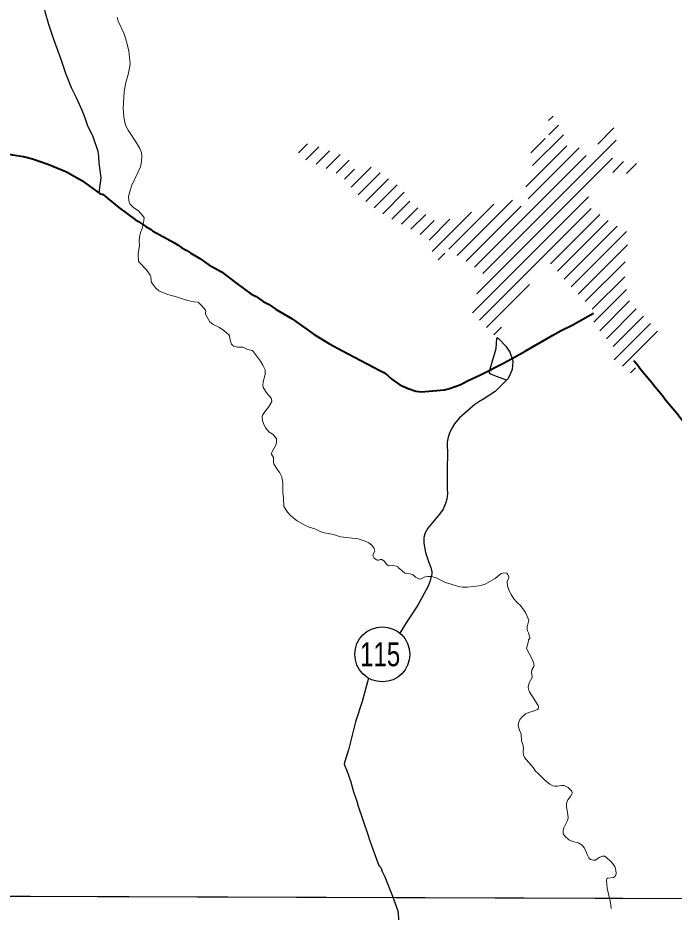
# Model space of a CAD drawing. Extents: x -1643653 to 4543381, y 1624270 to 13878484.
# Drawn here: x 614173 to 616089, y 8909821 to 8912433 of the extents above; entities that cross this region are included whole.
import ezdxf
from ezdxf.enums import TextEntityAlignment as Align

# ---------------------------------------------------------------- set-up
doc = ezdxf.new("R2010")
doc.units = 0
doc.header["$LTSCALE"] = 200
doc.layers.add('1', color=7, linetype='Continuous', lineweight=13)
doc.layers.add('6', color=7, linetype='Continuous', lineweight=13)

msp = doc.modelspace()

# ---------------------------------------------------------------- linework, layer by layer
at = {"layer": '1', "lineweight": 25}
msp.add_spline([(814781, 9009175.5), (814787.2, 9009173.4), (814796.9, 9009173.4), (814799.4, 9009172.4), (814805.1, 9009174.5), (814805.6, 9009176.5), (814811.7, 9009179.5), (814811.7, 9009179.5), (814801.5, 9009181), (814790.7, 9009181.5), (814784.1, 9009183.1), (814777.4, 9009185.1), (814778.4, 9009175.5)], degree=3, dxfattribs=at)
at = {"layer": '6'}
for p, q in [((615722.8, 8912133.8), (615735.8, 8912146.7)), ((615723.1, 8912091.6), (615751.6, 8912120.1)), ((615866.2, 8912064.9), (615913.5, 8912112.3)), ((615530.8, 8911687.2), (615920.2, 8912076.6)), ((615670.7, 8912039.2), (615712.3, 8912080.8)), ((615675.8, 8912001.9), (615765.9, 8912092)), ((614991.9, 8912039.2), (615018.6, 8912065.9)), ((615014.2, 8912019), (615051.5, 8912056.4)), ((615043.8, 8912006.3), (615082.5, 8912044.9)), ((615656.6, 8911940.3), (615776.4, 8912060.1)), ((615663.6, 8911904.8), (615812.3, 8912053.5)), ((615073.5, 8911993.6), (615114.1, 8912034.1)), ((615102.3, 8911979.9), (615140.1, 8912017.8)), ((615506.2, 8911705), (615832.4, 8912031.2)), ((615513.3, 8911627.3), (615909.8, 8912023.7)), ((615145.9, 8911938.7), (615204.6, 8911997.4)), ((615910.3, 8911981.8), (615942, 8912013.5)), ((615950.2, 8911979.3), (615979.5, 8912008.6)), ((615127, 8911962.2), (615156.3, 8911991.4)), ((615166.7, 8911917), (615230.7, 8911981)), ((615189.2, 8911897.1), (615255.5, 8911963.4)), ((615213, 8911878.5), (615280.3, 8911945.8)), ((615238.2, 8911861.3), (615301.4, 8911924.5)), ((615265.1, 8911845.7), (615317.8, 8911898.4)), ((615431.6, 8911757.6), (615562.9, 8911888.9)), ((615456.2, 8911739.8), (615617.5, 8911901.2)), ((615500.3, 8911571.8), (615839.7, 8911911.2)), ((615292.7, 8911830.9), (615340.7, 8911878.9)), ((615382.8, 8911751.2), (615497.4, 8911865.9)), ((615481.7, 8911722.9), (615642.7, 8911883.9)), ((615521.1, 8911550.2), (615847.5, 8911876.6)), ((615320.2, 8911816), (615363.8, 8911859.6)), ((615347.4, 8911800.8), (615388.4, 8911841.7)), ((615373.7, 8911784.6), (615434.8, 8911845.7)), ((615728.4, 8911715.1), (615872.1, 8911858.8)), ((615748.9, 8911693.2), (615897, 8911841.2)), ((615768.1, 8911669.9), (615923.5, 8911825.3)), ((615788.8, 8911648.1), (615950.1, 8911809.5)), ((615809.4, 8911626.3), (615953.2, 8911770.2)), ((615400.2, 8911726.3), (615420.1, 8911746.2)), ((615830, 8911604.6), (615946.5, 8911721.1)), ((615541.9, 8911528.6), (615667.5, 8911654.2)), ((615850.5, 8911582.5), (615945.5, 8911677.5)), ((615854.5, 8911544.2), (615950.1, 8911639.7)), ((615872.1, 8911519.3), (615959.2, 8911606.5)), ((615891.5, 8911496.3), (615978.4, 8911583.2)), ((615911.6, 8911474), (616000, 8911562.4)), ((615562.9, 8911507.2), (615585.5, 8911529.7)), ((615914.5, 8911434.4), (616020.8, 8911540.8)), ((615938.9, 8911416.4), (616040.5, 8911518)), ((615961.7, 8911396.8), (615976.5, 8911411.6)), ((574653.9, 8910009.3), (626625.7, 8909822.1))]:
    msp.add_line(p, q, dxfattribs=at)
at = {"layer": '6', "lineweight": 25}
msp.add_line((615138.8, 8910295.4), (615126.6, 8910258.3), dxfattribs=at)
for points in [[(614245.5, 8912486.2), (614248.5, 8912465.4), (614251.4, 8912452.5), (614261.7, 8912415.4), (614276.3, 8912371.6), (614298, 8912313.3), (614311.5, 8912271.9), (614311.5, 8912271.9), (614328.6, 8912229.8), (614343.1, 8912200.7), (614360.8, 8912161.7), (614367, 8912144.3)], [(614367, 8912144.3), (614375.3, 8912120.7), (614391.5, 8912087.1), (614405.8, 8912044.1), (614407.9, 8912028.6), (614409.2, 8912009.7), (614415.2, 8911965.8), (614409.2, 8911922.5)], [(615599.9, 8911375), (615570.6, 8911385.8), (615552.6, 8911394.1), (615550.1, 8911396.3), (615552, 8911408.1), (615569.5, 8911467.6), (615571.8, 8911497.7), (615572.6, 8911500), (615576.1, 8911497.3), (615598, 8911474.4), (615609.3, 8911456.9), (615617.4, 8911434.8), (615618, 8911429.4), (615616.8, 8911406.4), (615607.9, 8911385.5), (615603.3, 8911379.1), (615567.2, 8911342.2), (615530.8, 8911318.5), (615518.9, 8911311.9), (615507.1, 8911303.9), (615461.7, 8911264.1), (615448.1, 8911247.4), (615440.7, 8911235.9), (615434.2, 8911222.9), (615429.1, 8911208.4), (615426.1, 8911193.8), (615427.6, 8911155.1), (615426.4, 8911122.4), (615426.8, 8911058.8), (615427.6, 8911043.4), (615425.9, 8911028), (615422.1, 8911015), (615414.6, 8910998.4), (615403.9, 8910983.4), (615369.6, 8910943.1), (615362.5, 8910929), (615358.7, 8910915.2), (615358.7, 8910898.9), (615363.5, 8910871.4), (615371.8, 8910845.5), (615378.5, 8910828.5), (615382, 8910815.5), (615381.8, 8910809.8), (615377.1, 8910788.9), (615371.3, 8910773.5), (615341.2, 8910717.8), (615307.1, 8910666.5), (615288.4, 8910636.1)], [(615196.8, 8910504.9), (615177.9, 8910436.4), (615158.9, 8910377.1), (615138.8, 8910295.4)], [(615126.6, 8910258.3), (615125.9, 8910253.6), (615134.7, 8910231.8), (615144, 8910204.7), (615152.8, 8910172.4), (615162.3, 8910145.7), (615166.8, 8910130.4), (615195.1, 8910047.8), (615199.5, 8910032.8), (615209.6, 8910005.2)], [(615209.6, 8910005.2), (615227, 8909957.6), (615232.7, 8909951.5), (615237, 8909940.3), (615244.4, 8909924.9), (615267.1, 8909868.1), (615282, 8909824.9)], [(615282, 8909824.9), (615292.5, 8909716.1), (615320.5, 8909565.2), (615327.5, 8909531.6), (615344.7, 8909497.9), (615365.9, 8909445.9), (615390.2, 8909408.2), (615414.6, 8909376.6), (615454.1, 8909327.6), (615483.5, 8909293.9), (615556.6, 8909207.2), (615624.7, 8909143.6), (615643.3, 8909127.9), (615658.6, 8909118.9)]]:
    msp.add_lwpolyline(points, dxfattribs=at)
at = {"layer": '6'}
for points in [[(614462.6, 8912435.7), (614465.5, 8912423.8), (614481.8, 8912388.7), (614488.3, 8912371.2), (614496.7, 8912337), (614500.2, 8912308.2), (614500.5, 8912297.9), (614495.6, 8912271.6), (614487.7, 8912244.4), (614483.1, 8912218.1), (614480.7, 8912168.7), (614482.5, 8912145.7), (614484.5, 8912132.9)], [(614462.6, 8912435.7), (614465.5, 8912423.8), (614481.8, 8912388.7), (614488.3, 8912371.2), (614496.7, 8912337), (614500.2, 8912308.2), (614500.5, 8912297.9), (614495.6, 8912271.6), (614487.7, 8912244.4), (614483.1, 8912218.1), (614480.7, 8912168.7), (614482.5, 8912145.7), (614484.5, 8912132.9)], [(614484.5, 8912132.9), (614488.5, 8912118.5), (614494.8, 8912105.6), (614519, 8912068.7), (614528.5, 8912052.3), (614533.6, 8912040.3), (614535.2, 8912029.2), (614534.1, 8912013.9), (614530.5, 8911998.8), (614524.3, 8911983.7), (614505.6, 8911945.2), (614498.3, 8911923.7), (614495.8, 8911911), (614498.1, 8911894.5), (614499.6, 8911890.4), (614505.2, 8911884.2), (614511.7, 8911878.7), (614525.4, 8911869.5), (614537.6, 8911855.5), (614541.2, 8911849.9), (614540.9, 8911842.1), (614539, 8911829.5), (614535.8, 8911818.4), (614530.9, 8911806.4), (614528.1, 8911793), (614527.1, 8911782.7), (614527.6, 8911768.3), (614524, 8911744.5), (614525, 8911723.2), (614527.2, 8911719.7), (614548.6, 8911697.1), (614559.2, 8911682.3), (614561, 8911678.1), (614562.1, 8911665.3), (614563.3, 8911660.1), (614575.8, 8911644.3), (614584.1, 8911636.2)], [(614484.5, 8912132.9), (614488.5, 8912118.5), (614494.8, 8912105.6), (614519, 8912068.7), (614528.5, 8912052.3), (614533.6, 8912040.3), (614535.2, 8912029.2), (614534.1, 8912013.9), (614530.5, 8911998.8), (614524.3, 8911983.7), (614505.6, 8911945.2), (614498.3, 8911923.7), (614495.8, 8911911), (614498.1, 8911894.5), (614499.6, 8911890.4), (614505.2, 8911884.2), (614511.7, 8911878.7), (614525.4, 8911869.5), (614537.6, 8911855.5), (614541.2, 8911849.9), (614540.9, 8911842.1), (614539, 8911829.5), (614535.8, 8911818.4), (614530.9, 8911806.4), (614528.1, 8911793), (614527.1, 8911782.7), (614527.6, 8911768.3), (614524, 8911744.5), (614525, 8911723.2), (614527.2, 8911719.7), (614548.6, 8911697.1), (614559.2, 8911682.3), (614561, 8911678.1), (614562.1, 8911665.3), (614563.3, 8911660.1), (614575.8, 8911644.3), (614584.1, 8911636.2)], [(614584.1, 8911636.2), (614584.1, 8911636.2), (614608.1, 8911626), (614620.1, 8911622.5), (614632.8, 8911620.1), (614646.4, 8911614.5), (614669.5, 8911607.6), (614686.7, 8911603.6), (614699.1, 8911603.5)], [(614584.1, 8911636.2), (614584.1, 8911636.2), (614608.1, 8911626), (614620.1, 8911622.5), (614632.8, 8911620.1), (614646.4, 8911614.5), (614669.5, 8911607.6), (614686.7, 8911603.6), (614699.1, 8911603.5)], [(614699.1, 8911603.5), (614709.6, 8911592.7), (614721, 8911579.5), (614721.7, 8911577.4), (614720.5, 8911571.3), (614720.9, 8911568.5), (614725.2, 8911559.5), (614733.7, 8911545.2), (614743, 8911537.5), (614761.4, 8911528.7), (614774.6, 8911520.4), (614789, 8911508.1), (614790.7, 8911504.8), (614791.9, 8911496.1), (614796.7, 8911480.4), (614798.5, 8911478), (614803.8, 8911474.7), (614814.1, 8911471.6), (614829.7, 8911471.7), (614843.8, 8911465.2), (614857.7, 8911461.5)], [(614699.1, 8911603.5), (614709.6, 8911592.7), (614721, 8911579.5), (614721.7, 8911577.4), (614720.5, 8911571.3), (614720.9, 8911568.5), (614725.2, 8911559.5), (614733.7, 8911545.2), (614743, 8911537.5), (614761.4, 8911528.7), (614774.6, 8911520.4), (614789, 8911508.1), (614790.7, 8911504.8), (614791.9, 8911496.1), (614796.7, 8911480.4), (614798.5, 8911478), (614803.8, 8911474.7), (614814.1, 8911471.6), (614829.7, 8911471.7), (614843.8, 8911465.2), (614857.7, 8911461.5)], [(614857.7, 8911461.5), (614881.8, 8911430.8), (614888.6, 8911419.2), (614894.8, 8911405.2)], [(614857.7, 8911461.5), (614881.8, 8911430.8), (614888.6, 8911419.2), (614894.8, 8911405.2)], [(614894.8, 8911405.2), (614895.4, 8911391.4), (614888.9, 8911370.2), (614888.4, 8911360.8), (614889.1, 8911353.8), (614899.5, 8911337.6), (614912.4, 8911323), (614913.7, 8911319.3), (614914.2, 8911313.3), (614904.9, 8911296.6), (614891.1, 8911278.7), (614887.5, 8911272.7), (614886.7, 8911268.4), (614887.5, 8911257.1), (614891.3, 8911245.4), (614896.7, 8911234.7), (614905.3, 8911224.8), (614918.6, 8911216.5), (614926.2, 8911207.2), (614927.8, 8911204), (614928.2, 8911197.9), (614926.8, 8911187.5), (614914.6, 8911165.4), (614913.8, 8911159.4), (614919.2, 8911149.3), (614919.5, 8911135.1), (614920.4, 8911130.5), (614928.7, 8911116), (614938, 8911104.3), (614943.4, 8911093.3), (614946.1, 8911074.3), (614946.5, 8911046), (614948.7, 8911031.5), (614949.6, 8911006.3), (614960.5, 8910989.7), (614969.6, 8910979.2), (614979.4, 8910970.7), (614988.7, 8910963.9), (615010.6, 8910951.4), (615020.6, 8910946.9), (615040, 8910940.5), (615058, 8910932.4), (615068.1, 8910929.7), (615094.7, 8910924.8), (615114.8, 8910917.8), (615166.8, 8910911.8), (615187.2, 8910905), (615197.9, 8910900.2), (615206.5, 8910893.3), (615213.6, 8910883.4), (615215, 8910876), (615209.8, 8910865.4), (615209.1, 8910862.7), (615213.4, 8910855.6), (615220.2, 8910850.1), (615223.2, 8910849.3), (615226.8, 8910849.7), (615230.9, 8910851.5), (615235.7, 8910851.1), (615242.4, 8910846.7), (615250.7, 8910837.1), (615255.1, 8910833.3), (615267.9, 8910833.6), (615278.9, 8910832), (615282.1, 8910830.2)], [(614894.8, 8911405.2), (614895.4, 8911391.4), (614888.9, 8911370.2), (614888.4, 8911360.8), (614889.1, 8911353.8), (614899.5, 8911337.6), (614912.4, 8911323), (614913.7, 8911319.3), (614914.2, 8911313.3), (614904.9, 8911296.6), (614891.1, 8911278.7), (614887.5, 8911272.7), (614886.7, 8911268.4), (614887.5, 8911257.1), (614891.3, 8911245.4), (614896.7, 8911234.7), (614905.3, 8911224.8), (614918.6, 8911216.5), (614926.2, 8911207.2), (614927.8, 8911204), (614928.2, 8911197.9), (614926.8, 8911187.5), (614914.6, 8911165.4), (614913.8, 8911159.4), (614919.2, 8911149.3), (614919.5, 8911135.1), (614920.4, 8911130.5), (614928.7, 8911116), (614938, 8911104.3), (614943.4, 8911093.3), (614946.1, 8911074.3), (614946.5, 8911046), (614948.7, 8911031.5), (614949.6, 8911006.3), (614960.5, 8910989.7), (614969.6, 8910979.2), (614979.4, 8910970.7), (614988.7, 8910963.9), (615010.6, 8910951.4), (615020.6, 8910946.9), (615040, 8910940.5), (615058, 8910932.4), (615068.1, 8910929.7), (615094.7, 8910924.8), (615114.8, 8910917.8), (615166.8, 8910911.8), (615187.2, 8910905), (615197.9, 8910900.2), (615206.5, 8910893.3), (615213.6, 8910883.4), (615215, 8910876), (615209.8, 8910865.4), (615209.1, 8910862.7), (615213.4, 8910855.6), (615220.2, 8910850.1), (615223.2, 8910849.3), (615226.8, 8910849.7), (615230.9, 8910851.5), (615235.7, 8910851.1), (615242.4, 8910846.7), (615250.7, 8910837.1), (615255.1, 8910833.3), (615267.9, 8910833.6), (615278.9, 8910832), (615282.1, 8910830.2)], [(615282.1, 8910830.2), (615283.3, 8910828.4), (615301.8, 8910812), (615305.6, 8910810.9), (615317.4, 8910809.9), (615327, 8910806.2), (615334.1, 8910800.2), (615345.7, 8910794.2), (615350.8, 8910794.5), (615359.4, 8910799.7), (615362.8, 8910800.9), (615370.9, 8910802.2), (615381.1, 8910801.7), (615392.8, 8910798.4), (615422.1, 8910783.9), (615463.6, 8910771.7), (615471.6, 8910770.6), (615485.6, 8910770.5), (615518.7, 8910774.5), (615528.2, 8910776.4), (615537.8, 8910779.3), (615566.4, 8910796.3), (615584.6, 8910810.5), (615590.8, 8910812.2), (615600.7, 8910811.2), (615603.2, 8910808.9), (615606.8, 8910802), (615606.7, 8910796.5), (615602.9, 8910789.8), (615602.2, 8910786.7), (615603.2, 8910774.1), (615607.3, 8910759.9), (615613.3, 8910748.7), (615621.7, 8910736.7), (615632.2, 8910724.8), (615640.6, 8910717.5), (615655, 8910696.9)], [(615282.1, 8910830.2), (615283.3, 8910828.4), (615301.8, 8910812), (615305.6, 8910810.9), (615317.4, 8910809.9), (615327, 8910806.2), (615334.1, 8910800.2), (615345.7, 8910794.2), (615350.8, 8910794.5), (615359.4, 8910799.7), (615362.8, 8910800.9), (615370.9, 8910802.2), (615381.1, 8910801.7), (615392.8, 8910798.4), (615422.1, 8910783.9), (615463.6, 8910771.7), (615471.6, 8910770.6), (615485.6, 8910770.5), (615518.7, 8910774.5), (615528.2, 8910776.4), (615537.8, 8910779.3), (615566.4, 8910796.3), (615584.6, 8910810.5), (615590.8, 8910812.2), (615600.7, 8910811.2), (615603.2, 8910808.9), (615606.8, 8910802), (615606.7, 8910796.5), (615602.9, 8910789.8), (615602.2, 8910786.7), (615603.2, 8910774.1), (615607.3, 8910759.9), (615613.3, 8910748.7), (615621.7, 8910736.7), (615632.2, 8910724.8), (615640.6, 8910717.5), (615655, 8910696.9)], [(615655, 8910696.9), (615656, 8910695), (615665, 8910674.5), (615660.6, 8910655.1), (615659.8, 8910646.5), (615660.9, 8910642.9), (615664.4, 8910636.8), (615668, 8910623.7), (615667.6, 8910622), (615664, 8910616.7), (615663.2, 8910608.5), (615658, 8910591.3), (615674.8, 8910560.7), (615678.6, 8910550.5), (615680.5, 8910541.2), (615679.6, 8910538.6), (615673.4, 8910528.9), (615673.3, 8910520.8), (615674.8, 8910510.7), (615674.5, 8910507.1), (615665.9, 8910491.1), (615662.8, 8910478.6), (615664, 8910473.1), (615667.5, 8910464.5), (615692.6, 8910424.9), (615693.7, 8910422.2), (615692.8, 8910415.3), (615690.4, 8910413.3), (615677.6, 8910408), (615667.7, 8910405.9), (615654.9, 8910400.8), (615643.2, 8910389.5), (615638, 8910382.3), (615634.6, 8910373.3), (615634, 8910366.5), (615637.8, 8910353.2), (615642.9, 8910341.4), (615643.7, 8910321.8), (615647.4, 8910310.9), (615649.7, 8910301.3), (615648.6, 8910289.1), (615649.3, 8910280.6), (615652.9, 8910273.4), (615657.9, 8910266.5), (615678, 8910244), (615684.8, 8910233.2), (615691.8, 8910227.6), (615712.5, 8910205.7), (615726.4, 8910195.1), (615735.1, 8910190.5), (615740.5, 8910189), (615748.6, 8910189.6), (615760.2, 8910191.7), (615768.2, 8910191.4), (615779.6, 8910185.2), (615787.6, 8910178.1), (615790.3, 8910174.6), (615791.2, 8910169.9), (615790.2, 8910166.1), (615787, 8910159.5), (615778.9, 8910148.9), (615775.1, 8910139), (615775.4, 8910128.9), (615779, 8910106.3), (615779.6, 8910095.5)], [(615655, 8910696.9), (615656, 8910695), (615665, 8910674.5), (615660.6, 8910655.1), (615659.8, 8910646.5), (615660.9, 8910642.9), (615664.4, 8910636.8), (615668, 8910623.7), (615667.6, 8910622), (615664, 8910616.7), (615663.2, 8910608.5), (615658, 8910591.3), (615674.8, 8910560.7), (615678.6, 8910550.5), (615680.5, 8910541.2), (615679.6, 8910538.6), (615673.4, 8910528.9), (615673.3, 8910520.8), (615674.8, 8910510.7), (615674.5, 8910507.1), (615665.9, 8910491.1), (615662.8, 8910478.6), (615664, 8910473.1), (615667.5, 8910464.5), (615692.6, 8910424.9), (615693.7, 8910422.2), (615692.8, 8910415.3), (615690.4, 8910413.3), (615677.6, 8910408), (615667.7, 8910405.9), (615654.9, 8910400.8), (615643.2, 8910389.5), (615638, 8910382.3), (615634.6, 8910373.3), (615634, 8910366.5), (615637.8, 8910353.2), (615642.9, 8910341.4), (615643.7, 8910321.8), (615647.4, 8910310.9), (615649.7, 8910301.3), (615648.6, 8910289.1), (615649.3, 8910280.6), (615652.9, 8910273.4), (615657.9, 8910266.5), (615678, 8910244), (615684.8, 8910233.2), (615691.8, 8910227.6), (615712.5, 8910205.7), (615726.4, 8910195.1), (615735.1, 8910190.5), (615740.5, 8910189), (615748.6, 8910189.6), (615760.2, 8910191.7), (615768.2, 8910191.4), (615779.6, 8910185.2), (615787.6, 8910178.1), (615790.3, 8910174.6), (615791.2, 8910169.9), (615790.2, 8910166.1), (615787, 8910159.5), (615778.9, 8910148.9), (615775.1, 8910139), (615775.4, 8910128.9), (615779, 8910106.3), (615779.6, 8910095.5)], [(615779.6, 8910095.5), (615777.8, 8910089), (615767.1, 8910068), (615765.5, 8910058.6), (615765.6, 8910051.5), (615766.8, 8910047.7), (615773.9, 8910038.9), (615776.6, 8910037.6), (615782, 8910032.8), (615792.4, 8910027.4), (615808.9, 8910024.1), (615821.1, 8910017.4), (615827.3, 8910008), (615836, 8909987.3), (615840.8, 8909979.7), (615845.5, 8909975.1), (615853.4, 8909973.2), (615858.7, 8909973.1)], [(615779.6, 8910095.5), (615777.8, 8910089), (615767.1, 8910068), (615765.5, 8910058.6), (615765.6, 8910051.5), (615766.8, 8910047.7), (615773.9, 8910038.9), (615776.6, 8910037.6), (615782, 8910032.8), (615792.4, 8910027.4), (615808.9, 8910024.1), (615821.1, 8910017.4), (615827.3, 8910008), (615836, 8909987.3), (615840.8, 8909979.7), (615845.5, 8909975.1), (615853.4, 8909973.2), (615858.7, 8909973.1)], [(615858.7, 8909973.1), (615872.3, 8909982.2), (615872.3, 8909982.2), (615880.5, 8909984.9), (615885.6, 8909985), (615890.5, 8909981.6), (615906.4, 8909966.9), (615915.9, 8909954.7), (615919.4, 8909943.5), (615920.1, 8909933.2), (615918.5, 8909928), (615915.6, 8909924.2), (615912.6, 8909922.4), (615895.5, 8909920.7), (615893.3, 8909918.3), (615891.8, 8909914.3), (615893.8, 8909891.8), (615903, 8909853.2), (615904.8, 8909843), (615905.3, 8909832)], [(615858.7, 8909973.1), (615872.3, 8909982.2), (615872.3, 8909982.2), (615880.5, 8909984.9), (615885.6, 8909985), (615890.5, 8909981.6), (615906.4, 8909966.9), (615915.9, 8909954.7), (615919.4, 8909943.5), (615920.1, 8909933.2), (615918.5, 8909928), (615915.6, 8909924.2), (615912.6, 8909922.4), (615895.5, 8909920.7), (615893.3, 8909918.3), (615891.8, 8909914.3), (615893.8, 8909891.8), (615903, 8909853.2), (615904.8, 8909843), (615905.3, 8909832)]]:
    msp.add_lwpolyline(points, dxfattribs=at)
at = {"layer": '6', "lineweight": 40}
for points in [[(614095.5, 8912045.1), (614137.1, 8912037.7), (614156.6, 8912033.3), (614189.2, 8912028.5), (614215.5, 8912021.7), (614263.5, 8912005.4), (614314.9, 8911983.3), (614359.3, 8911958.1), (614413.5, 8911919.6), (614418.7, 8911918.6), (614421.7, 8911917.2), (614435.2, 8911906.1)], [(614435.2, 8911906.1), (614467.8, 8911879.5), (614516.5, 8911843.4), (614525, 8911838.5), (614546.8, 8911823.9), (614561.7, 8911815.5), (614566.3, 8911811.2), (614628, 8911777.5), (614641.1, 8911769.4), (614651.5, 8911761.7), (614666.3, 8911753.9), (614677.9, 8911746.1), (614704.5, 8911730.6), (614730.4, 8911712.3), (614767.2, 8911691.7), (614812.1, 8911658)], [(614812.1, 8911658), (614834.3, 8911641.2), (614853.5, 8911627.7), (614868.4, 8911619.3), (614889.4, 8911605.2), (614904.7, 8911597), (614927.5, 8911582), (614973.7, 8911554), (615037.8, 8911508.7), (615082.7, 8911481.4), (615119.3, 8911462), (615230, 8911403.5)], [(615622.9, 8911442.5), (615654.7, 8911459.9), (615735.5, 8911507.1), (615759.3, 8911519.9), (615791.8, 8911536), (615853.7, 8911570.5)], [(615230, 8911403.5), (615241.5, 8911397.4), (615253.3, 8911388.6), (615265.3, 8911377.7), (615288.5, 8911361.6), (615312.4, 8911350.8), (615334.8, 8911342.9), (615350.2, 8911341), (615419.2, 8911347.2), (615433.5, 8911350.8), (615466.3, 8911362.9), (615486, 8911373.3), (615523.5, 8911390.4), (615590.8, 8911424.9), (615622.9, 8911442.5)]]:
    msp.add_lwpolyline(points, dxfattribs=at)
at = {"layer": '6'}
msp.add_lwpolyline([(618535.2, 8909853.3), (607574.3, 8909890.7), (607543.3, 8898835.3), (618504.2, 8898795.8)], close=True, dxfattribs=at)
at = {"layer": '6', "lineweight": 25}
msp.add_circle((615237.1, 8910574.3), 80.3, dxfattribs=at)
at = {"layer": '6', "lineweight": 40}
msp.add_spline([(615971.7, 8911432.5), (616138.5, 8911227.2), (616313.3, 8911009), (616504.8, 8910771.9), (616895.5, 8910293.3), (617079.2, 8910062.8), (617725.5, 8909265.3), (618056.1, 8908857.7), (618263.2, 8908603.7), (618306.6, 8908556.9), (618336.6, 8908483.4), (618463.5, 8908212.8), (618533.7, 8908055.7), (618557.1, 8908012.3), (618590.5, 8907985.6), (618640.6, 8907962.2), (618764.1, 8907925.4), (618847.6, 8907882), (618877.7, 8907865.3), (618937.8, 8907811.8), (618997.9, 8907778.4), (619028, 8907745), (619141.5, 8907698.2), (619241.7, 8907674.8), (619372, 8907724.9), (619488.8, 8907801.8), (619552.3, 8907878.6), (619575.7, 8907905.4), (619599.1, 8907898.7), (619632.5, 8907871.9), (619679.2, 8907871.9), (619782.8, 8907918.7), (619872.9, 8907952.1), (619949.7, 8907952.1), (620026.6, 8907932.1), (620080, 8907908.7), (620120.1, 8907902), (620166.8, 8907932.1), (620233.6, 8907952.1), (620300.4, 8907958.8), (620363.9, 8907992.2), (620444, 8908052.4), (620517.5, 8908095.8), (620586.9, 8908115.3)], degree=3, dxfattribs=at)

# ---------------------------------------------------------------- texts
at = {"layer": '6', "width": 0.75}
msp.add_text('115', height=70, dxfattribs=at).set_placement((615230.8, 8910539.7), align=Align.CENTER)

doc.saveas('drawing.dxf')
